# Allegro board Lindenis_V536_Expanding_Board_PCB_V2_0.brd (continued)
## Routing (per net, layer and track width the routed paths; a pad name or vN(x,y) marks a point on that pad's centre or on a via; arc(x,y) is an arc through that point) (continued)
GND_SIGNAL: length 5.5
  TOP w0.406: U8.10 118.62,72.68 CG1.1 v1(119.46,72.43) ; U8.12 v1(117.55,74.88) ; v1(118.31,77.78) FB22.1 v1(118.31,79.45)
  vias: v1(106.05,75.31) v1(106.68,73.66) v1(107.06,70.74) v1(107.19,68.07) v1(108.08,75.06) v1(108.97,67.06) v1(109.35,64.9) v1(109.86,68.07) v1(110.24,69.6) v1(110.24,65.91) v1(110.74,72.26) v1(112.9,64.9) v1(113.41,67.94) v1(113.41,65.91) v1(113.92,72.52) v1(114.3,75.69) v1(114.3,74.8) v1(114.43,66.8) v1(114.68,73.66) v1(114.81,72.52) v1(114.81,70.61) v1(115.19,68.83) v1(115.7,74.68) v1(115.7,72.77) v1(115.82,75.56) v1(116.71,75.82) v1(118.01,82.68) v1(118.11,80.9) v1(118.87,76.07) v1(119.05,80.95) v1(119.13,77.09) v1(119.25,80.14) v1(119.51,74.8) v1(119.59,78.19) v1(120.52,73.28) v1(121.41,80.52) v1(121.41,78.99) v1(121.41,77.22) v1(121.41,74.93) v1(122.05,80.9) v1(122.3,80.14)
VBAT: length 8
  BOTTOM w0.508: 31.58,80.77 J11.7 ; J11.7 33.44,80.77 ; J11.7 32.51,81.7 ; J1.1 7.84,75.18 ; J1.1 7.84,73.53 ; J1.1 7.01,74.35 ; J1.1 8.67,74.35 ; 35.05,81.7 J11.5 34.12,80.77
  vias: v2(56.39,71.12) v2(56.39,70.36) v2(57.4,71.12) v2(57.4,70.36)
VCC33-AUDIO: length 8
  BOTTOM w0.254: R183.1 64.59,14.72 U23.7
  BOTTOM w0.508: C196.1 R183.1
  BOTTOM w0.762: FB12.2 62.16,17.14 C469.1 64.7,16.29 C196.1
VCC-1V8: length 8.9
  TOP w0.305: J7.18 122.92,42.06 122.68,42.29 122.95,42.56 J7.19 125.35,42.56 v1(125.91,42)
  TOP w0.508: U24.5 117.62,48.45 C302.2 118.97,48.21 C304.2
  BOTTOM w0.305: TP63.1 126.33,42.42 v1(125.91,42)
VCC-3V3: length 227.3
  TOP w0.254: v1(39.37,13.84) v1(39.37,14.35) ; v1(39.37,14.35) 39.02,14.7 UM2.21 ; v1(39.37,14.35) 39.32,14.3 UM2.20 ; v1(39.02,56.08) 41.55,58.62 41.55,60.83 40.54,61.85 39.27,61.85 39.09,61.67 v2(36.83,61.67) ; R531.2 v1(121.79,64.9) ; RL57.1 20.62,16.79 DL7.1 v1(21.21,17.02) ; UM2.23 38.98,15.5 v1(39.37,15.11) 39.36,15.1 UM2.22 ; R533.2 v1(121.79,64.01) ; J80.1 11.1,24.77 v1(11.81,24.05) ; R532.2 v1(121.79,65.79) ; RL12.1 15.57,16.23 DL6.1 v1(16.38,17.14) ; R550.1 v1(8.43,11.6) ; v1(77.98,81.03) 77.6,81.41 56.13,81.41 J36.2 ; R420.2 31.52,48.62 U51.1
  TOP w0.406: R192.1 C209.2 103.59,13.97 102.41,13.97 U902.7 ; RM53.2 RM7.2 ; R237.1 39.67,36.87 v1(39.06,36.26) U32.16 ; R420.2 C314.2 C313.2 ; v1(103,69.93) RG1.2 RG2.2 102.11,72.36 101.68,72.79 R13.2 101.68,73.94 Q2.1 ; U32.24 v1(39.05,41.46)
  TOP w0.508: DH12.1 v2(104.77,18.8) ; R238.1 R241.2 25.34,34.8 C328.1 ; v2(104.77,15.24) 104.69,15.32 R192.1 ; J11.8 33.44,78.23 ; J11.8 31.58,78.23 ; J11.8 32.51,79.16 ; RM4.2 v2(21.34,73.03) ; C313.2 v2(31.75,49.78) ; 54.86,81.67 J36.2 ; J36.2 53.86,82.68 ; J36.2 54.86,83.68 ; J11.6 35.05,79.16 ; J11.6 35.98,78.23 ; J11.6 34.12,78.23 ; U11.14 95.5,78.53 ; U11.14 96.43,77.6 ; U11.14 100.33,72.77 v1(100.33,70.23) 100.33,61.85 100.91,61.27 RP84.2 ; U11.14 95.5,76.67 ; RM7.2 36.78,61.72 v2(36.83,61.67)
  L3SIG w0.508: U11.14 95.5,78.53 ; U11.14 94.58,77.6 ; U11.14 95.5,76.67 ; U11.14 96.43,77.6
  BOTTOM w0.254: v1(11.81,24.05) 11.86,24 12.57,24 13.59,22.99 13.59,19.94 v1(16.38,17.14) 14.73,15.49 14.73,12.83 13.08,11.18 11.68,11.18 11.26,11.6 v1(8.43,11.6) ; v1(121.79,65.79) v1(121.79,64.9) v1(121.79,64.01)
  BOTTOM w0.406: v1(16.38,17.14) 16.51,17.02 v1(21.21,17.02) 33.27,17.02 ; v1(100.33,70.23) 102.69,70.23 v1(103,69.93) 108.92,64.01 v1(121.79,64.01) ; v1(39.05,41.46) v1(39.05,37.85) 39.05,36.27 v1(39.06,36.26) 39.06,32.38 U12.14
  BOTTOM w0.508: U12.13 37.64,29.79 ; U12.13 37.64,28.14 ; U12.13 36.81,28.96 ; U12.13 38.47,28.96 ; U11.14 96.43,77.6 ; U11.14 95.5,78.53 ; U11.14 95.5,76.67 ; 54.86,81.67 J36.2 ; J36.2 54.86,83.68 ; J36.2 53.86,82.68 ; J36.2 55.87,82.68 ; U12.14 38.47,30.96 ; U12.14 37.64,30.14 ; U12.14 37.64,31.79 ; RC1.1 v2(90.55,20.08) ; J11.8 30.73,76.45 28.58,76.45 25.15,73.03 v2(21.34,73.03)
  BOTTOM w0.762: R39.1 36.96,76.33 J11.6 J11.8
  vias: v1(46.61,83.19) v1(46.61,82.68) v1(78.49,81.03) v1(81.03,81.03) v1(81.53,81.03) v2(23.88,35.94) v2(23.88,35.18) v2(24.77,35.94) v2(46.48,60.58) v2(47.23,60.62) v2(48.01,60.63) v2(80.64,63.25) v2(81.15,63.75) v2(81.66,64.39) v2(97.16,78.23) v2(97.16,77.47) v2(100.08,60.33) v2(100.33,55.37) v2(100.84,60.33) v2(101.09,55.37)
VCC-5V: length 59.6
  TOP w0.254: v1(105.92,17.65) 107.19,17.65 107.7,17.14 RH18.1 RH17.1
  TOP w0.305: v1(108.58,12.83) 108.66,12.75 109.6,12.75 110.43,11.92 JH1.18
  TOP w0.406: v1(102.87,27.3) 102.87,34.98 CL60.1 ; v1(108.58,12.83) 107.7,13.72 CH2.1
  TOP w0.508: U22.1 53.31,76.13 ; U22.1 52.51,75.33 ; U22.1 54.11,75.33 ; 87.88,76.67 U11.8 ; U11.8 88.81,77.6 ; U11.8 86.96,77.6 ; J11.3 37.59,81.7 ; J11.3 38.52,80.77 ; J11.3 37.59,79.84 ; 39.2,80.77 J11.1 ; J11.1 40.13,81.7 ; J11.1 40.13,79.84 ; J11.1 41.06,80.77
  L3SIG w0.508: 53.31,74.53 U22.1 52.51,75.33 ; 37.59,79.84 J11.3 ; J11.3 38.52,80.77 ; J11.3 36.66,80.77 ; J11.3 37.59,81.7 ; J11.1 40.13,81.7 ; J11.1 41.06,80.77 ; J11.1 39.2,80.77 ; J11.1 40.13,79.84
  BOTTOM w0.406: v1(108.58,12.83) 107.7,12.83 105.92,14.61 v1(105.92,17.65) 105.92,18.92 105.28,19.56 104.67,19.56 104.27,19.96 104.27,24.38 102.87,25.78 v1(102.87,26.54)
  BOTTOM w0.508: U11.8 87.5,77.98 C458.2 88.36,79.84 C457.2 ; U11.8 88.81,77.6 ; U11.8 87.88,78.53
  vias: v1(103.38,27.3) v1(103.38,26.54) v2(9.91,22.61) v2(9.91,21.84) v2(9.91,21.08) v2(9.91,15.37) v2(9.91,14.61) v2(10.67,22.61) v2(10.67,21.84) v2(10.67,21.08) v2(10.67,15.37) v2(10.67,14.61) v2(11.43,15.88) v2(12.19,15.88) v2(37.34,20.95) v2(37.84,21.62) v2(38.1,20.95) v2(38.61,21.59) v2(52.32,71.12) v2(52.32,70.36) v2(52.45,60.48) v2(53.09,71.12) v2(53.09,70.36) v2(53.21,60.48) v2(53.85,71.12) v2(53.85,70.36) v2(53.98,60.48) v2(54.74,60.48) v2(55.5,60.48)
VCC-PE: length 29
  TOP w0.406: RP85.1 41.57,70.91 v1(42.8,72.14) ; v1(41.73,79.76) v1(45.97,79.76)
  BOTTOM w0.406: 54.36,79.5 53.59,78.74 49.28,78.74 48.26,79.76 v1(45.97,79.76) ; 54.36,79.5 54.36,76.93 55.31,75.98 U22.3 ; 54.36,79.5 54.36,79.71 RP82.1 ; v1(41.73,79.76) 41.91,79.58 41.91,78.11 43.31,76.71 43.31,72.54 42.9,72.14 v1(42.8,72.14)
VCC-RTC: length 45.3
  TOP w0.508: 54.99,68.91 v2(54.99,70.23) ; J11.20 17.93,78.23 22.17,73.99 v1(33.17,73.99) ; v2(39.67,73.87) 42.46,73.87 v2(44.2,72.14)
  BOTTOM w0.508: v2(54.99,70.23) 54.99,71.5 54.36,72.14 50.42,72.14 48.77,73.79 44.7,73.79 44.2,73.28 v2(44.2,72.14) ; v2(39.67,73.87) C84.2 36.16,73.87 C385.2 34.19,74.22 D608.2 33.43,74.24 v1(33.17,73.99)
VCC-WIFI-IO: length 25.4
  TOP w0.508: v2(39.13,55.37) 42.04,58.27 42.04,61.21 40,63.25 40,68.58 38.82,69.77 RP81.1
  BOTTOM w0.508: U13.14 35.63,55.54 36.73,56.64 C467.1 40.22,55.66 C170.1 v2(39.13,55.37)
4G-STATUS: length 82.6
  TOP w0.102: v1(89.28,34.8) 89.28,23.72 86.64,21.08 80.52,21.08 79.12,19.68 U901.105 ; v1(119.13,49.15) 118.75,49.53 111.51,49.53 110.11,50.93 108.33,50.93 103.12,56.13 97.92,56.13 v1(97.03,55.24)
  BOTTOM w0.102: U27.49 123.67,48.24 123.19,47.75 123.19,47.37 122.81,46.99 122.43,46.99 120.27,49.15 v1(119.13,49.15) ; v1(97.03,55.24) 95.45,53.67 95.45,36.14 94.11,34.8 v1(89.28,34.8)
ALDO1: length 152.9
  TOP w0.254: v1(78.61,79.12) v1(81.66,79.12) ; v1(92.81,22.33) 92.81,22.37 92.76,22.42 92.76,40.7 93.52,41.46 93.52,50.11 91.43,52.21 v2(90.42,52.21) ; v1(96.75,18.39) 96.75,14.63 99.1,12.28 RK1.2
  TOP w0.508: v2(83.06,54.99) 83.06,65.15 v1(82.33,65.88) 81.91,66.29 72.26,66.29 71.73,66.83 48.59,66.83 47.37,68.05 U901.38 ; v2(88.39,54.74) 88.39,54.24 v2(90.42,52.21)
  TOP w0.762: J11.16 22.35,77.32 23.49,76.17 35.64,76.17 36.09,75.72 42.77,75.72 47.37,71.12 U901.38
  BOTTOM w0.254: v1(82.33,65.88) 82.33,66.35 84.71,68.73 84.71,70.43 84,71.15 84,72.34 81.56,74.78 81.56,79.02 v1(81.66,79.12) ; v1(78.61,79.12) 78.61,79.02 78.16,78.56 77.64,78.56 77.39,78.82 RK8.2 ; v1(92.81,22.33) v1(96.75,18.39)
  BOTTOM w0.508: v2(83.06,54.99) 88.14,54.99 v2(88.39,54.74)
ALDO3: length 256.8
  TOP w0.254: JL6.4 v1(124.72,64.64) ; CL13.1 v1(123.83,61.34)
  TOP w0.406: 46.32,67.98 48.16,66.14 56.97,66.14 57.38,65.74 81.58,65.74 82.4,64.92 v1(82.4,54.99) ; v1(43,69.85) 42.67,69.51 42.67,60.66 v1(42.6,60.58) ; v1(93.55,65.68) 91.68,65.68 90.65,64.66 90.65,58.78 v1(90.75,58.67) 93.95,55.47 93.95,41.28 93.19,40.52 93.19,22.89 93.47,22.61 v1(93.47,22.32) ; v2(44.73,69.98) 45.54,69.16 U901.39 ; CL13.1 v1(123.23,60.75) ; U902.3 99.17,14.8 C210.2 99.1,15.07 97.36,16.82 v1(97.36,18.44)
  TOP w0.508: 46.32,67.98 46.1,68.2 U901.39 46.1,71.25 42.67,74.68 39.17,74.68 38.76,74.27 35.51,74.27 34.52,75.26 23.06,75.26 21.08,77.24 21.08,79.5 J11.17
  BOTTOM w0.254: v1(42.6,60.58) 42.6,60.46 40.66,58.52 35.89,58.52 34.42,57.05 27.74,57.05 26.85,56.16 23.32,56.16 21.32,54.16 Q23.1 ; R78.2 R77.2 86.01,80.32 86.01,83.09 86.74,83.82 88.01,83.82 89.15,82.68 J35.2 ; v1(93.47,22.32) 93.47,22.25 96.9,18.82 96.98,18.82 v1(97.36,18.44) ; v1(124.72,64.64) 124.72,62.23 v1(123.83,61.34)
  BOTTOM w0.406: J35.2 90.12,82.68 94.23,78.56 94.23,76.15 94.36,76.02 94.36,73.28 93.55,72.47 v1(93.55,65.68) 95.76,63.47 95.76,62.61 98.81,59.56 122.05,59.56 v1(123.23,60.75) ; v1(82.4,54.99) 82.4,55.22 85.85,58.67 v1(90.75,58.67) ; v1(43,69.85) 43,69.87 43.11,69.98 v2(44.73,69.98)
ANT-BIAS: length 2.2
  TOP w0.102: U8.9 118.87,71.58 CG1.2
AP-WAKE-4G: length 39.2
  TOP w0.102: U901.108 82.93,19.81 83.31,20.19 86.61,20.19 90.3,23.88 v1(90.3,33.78)
  BOTTOM w0.102: U27.72 107.97,32.87 107.06,33.78 v1(90.3,33.78)
AP-WAKE-BT: length 73.7
  TOP w0.102: v1(87.12,66.55) 87.38,66.8 U901.155
  BOTTOM w0.102: 87,66.67 87,66.67 87,71.71 R528.2 ; 87,66.67 86.62,66.67 81.08,61.14 45.11,61.14 41.17,57.2 36.41,57.2 34.67,55.47 34.67,53.88 U13.13 ; 87,66.67 v1(87.12,66.55)
AUDIO-L: length 6.4
  TOP w0.254: v1(54.61,13.21) 54.53,13.29 D609.2 53.56,12.87 53.56,10.75 J79.4
  BOTTOM w0.254: R180.2 54.86,13.46 v1(54.61,13.21)
AUDIO-R: length 25.8
  TOP w0.254: v1(58.17,10.41) 56.9,11.68 56.9,12.57 55.71,13.76 ; 55.71,13.76 D610.2 ; 55.71,13.76 55.71,13.16 54.36,11.81 54.36,7.25 J79.2
  BOTTOM w0.254: R181.1 66.04,13.34 66.67,12.7 66.67,11.18 65.91,10.41 v1(58.17,10.41)
AVDUSB: length 21.3
  TOP w0.508: U8.7 116.08,67.48 115.57,66.97 115.57,61.98 114.3,60.71 111.25,60.71 109.86,59.31 104.14,59.31 102.87,60.58 RP75.2
BATT-VCC-3V3: length 8.4
  BOTTOM w0.406: R43.2 41.77,71.82 U2.1 41.07,71.82 C85.2 41.07,74.8 D7.2
  BOTTOM w0.508: U3.1 45.17,70.99 42.59,70.99 R43.2
BATT-VCC-RTC: length 7.5
  BOTTOM w0.254: R45.2 37.64,70.27 38.63,71.26 38.63,71.82
  BOTTOM w0.508: D608.1 34.19,72.85 C81.2 36.48,72.18 C82.2 38.26,72.18 38.63,71.82 U2.5
BB-PWREN: length 31.8
  TOP w0.102: v1(89.92,43.18) 89.92,23.78 86.58,20.45 82.42,20.45 81.66,19.68 U901.107
  BOTTOM w0.102: v1(89.92,43.18) 89.66,42.93 88.9,42.93 88.6,42.63 RL70.2
BB_PW: length 26.6
  TOP w0.102: RL38.2 99.87,38.31 97.49,40.68 94.15,40.68 93.6,40.13 93.6,23.93 93.9,23.62 U901.121
BLDO1: length 32.3
  TOP w0.508: U901.40 43.94,69.14 43.94,69.89 43.43,70.4 43.19,70.4 43.18,70.4 42.72,70.4 42.72,70.4 41.91,69.6 41.28,69.6 40.72,70.15 RP85.2 RP81.2 39.67,72.39 38.55,73.51 35.33,73.51 34.24,74.6 22.63,74.6 19.81,77.42 J11.18
BT-RST-N: length 72.8
  TOP w0.102: U901.156 94.49,68.07 93.47,67.06 86.55,67.06 v1(86.52,67.02)
  BOTTOM w0.102: R526.2 86.74,71.08 86.74,67.25 v1(86.52,67.02) 86.52,66.86 81,61.34 45.03,61.34 41.09,57.4 36.32,57.4 33.84,54.93 U13.12
BT-UART-CTS: length 73.8
  TOP w0.102: v1(85.91,67.5) 85.95,67.46 93.25,67.46 94.36,68.58 U901.1
  BOTTOM w0.102: v1(85.91,67.5) 85.95,67.46 85.95,66.89 80.81,61.75 44.86,61.75 40.92,57.81 36.15,57.81 34.6,56.26 28.32,56.26 27.63,55.57 U13.6
BT-UART-RTS: length 75.1
  TOP w0.102: v1(86.36,67.82) 86.36,67.82 92.58,67.82 93.09,68.33 U901.2
  BOTTOM w0.102: U13.8 29.63,55.41 30.1,55.88 34.51,55.88 36.24,57.61 41,57.61 44.94,61.54 80.89,61.54 86.16,66.82 86.16,67.17 86.36,67.37 v1(86.36,67.82) 86.36,70.57 R525.2
BT-UART-RX: length 68.5
  TOP w0.102: U901.9 84.58,68.53 84.58,67.16 84.61,67.13 v1(84.61,67.11)
  BOTTOM w0.102: U13.2 24.58,55.88 27.08,55.88 27.91,56.72 34.49,56.72 35.98,58.22 40.75,58.22 44.69,62.15 80.59,62.15 84.61,66.17 v1(84.61,67.11)
BT-UART-TX: length 66.9
  TOP w0.102: 85.47,68.91 85.47,68.07 v1(84.96,67.56)
  BOTTOM w0.102: U13.4 26.45,54.93 28.04,56.52 34.57,56.52 36.07,58.01 40.84,58.01 44.77,61.95 80.72,61.95 84.96,66.19 v1(84.96,67.56)
BT-WAKE-AP: length 112.3
  TOP w0.102: v1(87.25,23.24) 68.43,23.24 65.25,20.07 52.2,20.07 46.61,25.65 46.61,35.53 47.45,36.36 47.45,52.27 48.06,52.88 49.66,52.88 50.88,54.1 50.88,59.9 51.03,60.05 51.03,60.47 50.82,60.68 50.02,60.68 49.66,60.33 v1(49.66,60.33) ; U901.120 v1(93.98,22.35)
  BOTTOM w0.102: v1(87.25,23.24) 93.09,23.24 v1(93.98,22.35) ; v1(49.66,60.33) 49.5,60.17 47.35,60.17 38.74,51.56 34.42,51.56 33.63,52.35 U13.11
CLKOUT-125M: length 1.8
  TOP w0.102: UM1.35 25.2,67.42 RM14.1
CSI0-D0: length 22.7
  BOTTOM w0.102: U22.11 62.48,76.15 62.48,78.11 63.5,79.12 71.32,79.12 73.22,77.23 73.22,76.18 R434.2
CSI0-D1: length 18.7
  BOTTOM w0.102: U22.12 63.31,78.35 63.83,78.87 71.2,78.87 72.82,77.24 72.82,76.12 76.58,72.36 R435.2
CSI0-D2: length 18.2
  BOTTOM w0.102: U22.13 64.14,76.5 64.14,77.98 64.77,78.61 69.32,78.61 70.31,77.62 70.31,76.94 70.93,76.32 71.79,76.32 74.17,73.94 R436.2
CSI0-D3: length 11.5
  BOTTOM w0.102: R437.2 71.04,72.26 70.13,72.26 68.2,74.19 68.2,77.57 67.64,78.13 66.11,78.13 U22.14
CSI0-D4: length 4.9
  BOTTOM w0.102: R438.2 69.98,71.98 67.31,74.65 U22.15
CSI0-D5: length 6.9
  BOTTOM w0.102: U22.16 66.42,76.44 66.42,75.03 68,73.46 68,71.75 R439.2
CSI0-D6: length 15.5
  BOTTOM w0.102: R440.2 67.54,71.77 67.54,73.28 66.17,74.65 66.17,75.82 65.66,76.33 64.9,76.33 64.39,76.83 64.39,77.72 65.02,78.36 68.1,78.36 68.45,78 68.45,76.18 U22.17
CSI0-D7: length 7.3
  BOTTOM w0.102: U22.18 70.36,76.28 70.36,74.68 72.9,72.14 R441.2
CSI0-HSYNC: length 33
  BOTTOM w0.102: U22.9 60.31,76.33 58.8,76.33 58.29,76.83 58.29,78.87 60.2,80.77 72.19,80.77 77.39,75.56 77.39,74.54 R432.2
CSI0-MCLK: length 26.5
  TOP w0.102: v1(81.03,71.5) v1(78.49,71.5)
  BOTTOM w0.102: R431.2 81.07,71.54 v1(81.03,71.5) ; v1(78.49,71.5) 78.49,71.73 78.19,72.02 78.19,72.53 77.86,72.86 77.36,72.86 73.85,76.37 73.85,77.33 71.5,79.68 62.32,79.68 C456.1 61.31,78.66 U22.10
CSI0-PCLK: length 36.4
  BOTTOM w0.102: U22.5 57.31,75.91 56.26,76.96 56.26,78.49 59.08,81.31 72.44,81.31 78.23,75.51 78.23,74.22 79.81,72.64 82.04,72.64 83.06,71.63 R430.2
CSI0-PWR: length 14.3
  TOP w0.102: v1(63.25,71.73) 63.14,71.63 59.31,71.63 v1(59.05,71.37)
  BOTTOM w0.102: v1(59.05,71.37) 59.05,71.75 56.39,74.42 54.74,74.42 54.36,74.8 54.36,76.28 U22.2 ; R522.2 63.3,71.67 v1(63.25,71.73)
CSI0-RSET: length 16.1
  TOP w0.102: v1(59.05,70.87) 59.56,71.37 v1(65.79,71.37)
  BOTTOM w0.102: R442.2 65.96,71.54 v1(65.79,71.37) ; U22.4 56.26,76.38 56.26,74.93 59.56,71.63 59.56,71.37 v1(59.05,70.87)
CSI0-SCK: length 9.6
  TOP w0.102: v1(59.87,70.36) 60.07,70.15 U901.28
  BOTTOM w0.102: v1(59.87,70.36) 59.87,71.83 58.29,73.41 58.29,75.95 57.31,76.93 U22.6
CSI0-SDA: length 7.8
  TOP w0.102: U901.27 61.34,69.39 v1(60.38,70.36)
  BOTTOM w0.102: U22.7 58.7,74.72 58.7,73.51 60.38,71.83 v1(60.38,70.36)
CSI0-VSYNC: length 26.2
  BOTTOM w0.102: R433.2 79.12,72.44 74.43,77.14 74.43,77.52 71.7,80.24 60.81,80.24 59.31,78.74 U22.8
CTP-INT: length 86.3
  TOP w0.102: JL6.2 125.11,63.64 123.7,62.23 C464.2 122.83,61.83 121.72,61.83 121.36,61.47 121.36,60.27 120.14,59.05 112.39,59.05 110.46,57.12 105.51,57.12 105.43,57.05 104.8,57.05 v1(104.77,57.02) ; v1(88.14,57.53) 85.34,54.74 85.34,53.21 91.31,47.24 91.31,22.13 93.38,20.07 93.98,20.07 94.36,19.68 U901.117
  BOTTOM w0.102: v1(88.14,57.53) 88.39,57.78 91.11,57.78 92.05,58.72 95.58,58.72 97.21,57.1 104.7,57.1 v1(104.77,57.02)
CTP-RST: length 87.4
  TOP w0.102: JL6.3 123.96,64.14 v1(123.83,64.01) R533.1 C465.2 123.1,63.12 122.7,63.52 121.81,63.52 121.16,62.87 121.16,60.36 120.06,59.26 112.31,59.26 110.46,57.4 v1(105.28,57.4) ; v1(87.63,57.53) 85.14,55.04 85.14,53.13 91.11,47.16 91.11,22.05 93.09,20.07 U901.116
  BOTTOM w0.102: v1(87.63,57.53) 87.64,57.53 88.27,58.17 91.19,58.17 91.95,58.93 95.66,58.93 97.29,57.3 104.41,57.3 104.49,57.38 105.26,57.38 v1(105.28,57.4)
DC1SW: length 275.7
  TOP w0.254: v1(121.54,48.51) 121.79,48.77 121.79,52.32 ; v2(33.78,9.4) 33.78,10.08 RL47.2 ; R269.2 114.98,48.68 115.44,49.15 v1(118.62,49.15)
  TOP w0.305: J7.38 122.95,52.06 122.68,52.32 122.91,52.56 J7.39 125.56,52.56 v1(125.95,52.17) ; C463.2 v2(121.23,56.01) 121.23,56.44 120.1,57.57 R320.2
  TOP w0.508: J11.15 23.62,79.5 23.62,77.65 24.26,77.01 36.02,77.01 36.58,76.45 43.18,76.45 48.64,70.99 U901.37 48.64,68.07 49.15,67.56 71.88,67.56 72.39,67.06 82.04,67.06 83.82,65.28 v2(83.82,55.75) 83.82,54.36 83.31,53.85 53.85,53.85 51.94,51.94 v2(51.94,51.69) ; v2(48.13,9.4) v2(33.78,9.4) ; v2(47.37,34.04) 47.55,33.86 47.55,25.91 v2(52.68,20.78)
  BOTTOM w0.254: v1(121.54,48.51) 120.4,49.66 119,49.66 118.62,49.28 v1(118.62,49.15)
  BOTTOM w0.305: TP66.1 v1(125.95,52.17)
  BOTTOM w0.508: v2(33.78,9.4) 33.15,8.76 30.35,8.76 28.52,10.59 17.75,10.59 C111.1 17.37,10.21 C112.1 16.51,7.37 15.37,6.22 15.37,4.45 J82.20 J82.18 ; v2(52.68,20.78) 52.6,20.78 48.13,16.31 v2(48.13,9.4) ; v2(51.94,51.69) 51.89,51.74 48.31,51.74 47.37,50.8 v2(47.37,34.04) ; v2(121.23,56.01) 120.6,55.37 119,55.37 117,57.37 110.45,57.37 109.27,56.18 97.36,56.18 95.38,58.17 92.2,58.17 91.31,57.28 88.9,57.28 87.38,55.75 v2(83.82,55.75)
DM1_USB: length 64.2
  TOP w0.114: U32.27 37.62,43.41 37.77,43.56 v1(39.24,43.56) ; v1(86.74,53.72) 86.76,53.74 87.05,53.74 92.09,48.71 92.39,48.71 v1(92.71,48.39)
  BOTTOM w0.114: v1(86.74,53.72) 86.48,53.72 85.97,53.21 48.44,53.21 40.82,45.59 40.82,44.93 39.44,43.56 v1(39.24,43.56) ; U27.12 92.86,48.24 v1(92.71,48.39)
DM2_USB: length 29.3
  TOP w0.114: J9.3 13.15,37.48 13.26,37.36 14.25,37.36 15.62,38.73 16.68,38.73 D28.1 17.39,38.7 18.76,38.7 21.21,41.15 21.21,45.09 24.38,48.26 27.69,48.26 28.96,46.99 28.96,43.58 29.36,43.18 29.46,43.18 29.7,43.41 U32.2
DM3_USB: length 25.7
  TOP w0.114: J9.7 10.44,37.48 10.55,37.36 11.53,37.36 11.94,36.96 11.94,35.43 12.32,35.05 14.78,35.05 14.95,34.89 16.64,34.89 D29.1 17.39,34.89 18.38,34.89 23.88,40.39 28.32,40.39 29.33,39.38 29.64,39.38 29.77,39.51 U32.8
DM4_USB: length 2.4
  TOP w0.114: U32.11 31.27,37.56 v1(31.5,37.34)
  BOTTOM w0.114: v1(31.5,37.34) 31.62,37.34 TP87.1
DP1_USB: length 64.2
  TOP w0.114: v1(87.12,54.1) 92.21,49.01 92.7,49.01 v1(92.71,49.02) ; U32.28 37.62,44.06 37.82,43.87 38.99,43.87 v1(39.24,44.12)
  BOTTOM w0.114: v1(92.71,49.02) 92.92,49.24 U27.13 ; v1(39.24,44.12) 39.27,44.09 39.55,44.09 40.51,45.06 40.51,45.72 48.31,53.52 85.85,53.52 86.43,54.1 v1(87.12,54.1)
DP2_USB: length 29.3
  TOP w0.114: J9.2 13.15,36.94 13.26,37.06 14.38,37.06 15.75,38.43 16.6,38.43 D27.1 17.39,38.39 18.88,38.39 21.51,41.02 21.51,44.96 24.51,47.96 27.56,47.96 28.65,46.86 28.65,43.46 29.23,42.88 29.61,42.88 29.72,42.76 U32.3
DP3_USB: length 25.7
  TOP w0.114: U32.9 29.77,38.86 29.56,39.07 29.2,39.07 28.19,40.08 24,40.08 18.5,34.58 17.39,34.58 D30.1 16.64,34.58 14.82,34.58 14.66,34.75 12.19,34.75 11.63,35.31 11.63,36.83 11.41,37.06 10.55,37.06 10.44,36.94 J9.6
DP4_USB: length 2.3
  TOP w0.114: U32.12 31.41,36.91 v1(31.5,36.83)
  BOTTOM w0.114: TP88.1 31.75,36.83 v1(31.5,36.83)
EPHY-CLK-25M: length 1.9
  TOP w0.102: U901.24 v1(65.15,70.1)
  BOTTOM w0.102: RM56.2 v1(65.15,70.1)
FEL: length 60.3
  TOP w0.102: v1(118.11,17.4) 118.28,17.23 RK7.2 ; U901.95 66.42,18.29 66.83,17.88 69.46,17.88 72.01,15.33 72.01,13.84 73.91,11.94 v1(96.9,11.94)
  BOTTOM w0.102: v1(96.9,11.94) 109.6,11.94 111.51,13.84 117.12,13.84 117.6,14.32 117.6,16.89 v1(118.11,17.4)
GPADC0: length 134.3
  TOP w0.102: v1(89.26,65.33) 89.26,65.28 89.18,65.2 89.18,62.38 88.77,61.98 88.77,60.17 84.73,56.13 84.73,52.96 88.9,48.79 88.9,23.88 86.31,21.29 69.93,21.29 68.96,20.32 U901.97 68.96,18.19 69.06,18.08 69.67,18.08 72.26,15.49 72.26,13.88 74,12.14 96.34,12.14 96.49,12.29 98.03,12.29 RK1.1 DK1.2 CK1.2 RK2.2 ; v1(91.57,79.12) 90.8,79.88 81.57,79.88 78.99,82.46 J33.1
  BOTTOM w0.102: v1(91.57,79.12) 91.82,78.87 91.82,74.3 90.75,73.23 90.75,65.7 90.53,65.48 89.41,65.48 v1(89.26,65.33)
GPADC1: length 105.7
  TOP w0.102: v1(90.93,79.12) 90.42,79.63 81.53,79.63 80.9,80.26 78.74,80.26 78.49,80.01 75.79,80.01 v1(75.69,80.11) ; v1(88.85,65.68) 88.85,62.43 88.53,62.12 88.53,61.07 88.52,61.06 88.52,60.21 84.53,56.22 84.53,52.88 88.6,48.81 88.6,24 86.18,21.59 68.96,21.59 67.69,20.32 U901.96
  BOTTOM w0.102: v1(88.85,65.68) 90.45,65.68 90.55,65.79 90.55,73.31 91.62,74.38 91.62,78.44 v1(90.93,79.12) ; v1(75.69,80.11) 75.69,79.89 RK8.1 CK16.2 DK2.2 76.54,82.59 J33.2
GPS-RESETN: length 108.7
  TOP w0.102: v1(97.79,59.82) 99.16,58.45 110.32,58.45 111.74,59.87 117.93,59.87 118.24,60.17 118.24,70.18 117.93,70.48 U8.8 ; U901.57 46.1,46.48 46.53,46.91 46.53,52.5 48.13,54.1 48.72,54.1 v1(48.84,54.23)
  BOTTOM w0.102: R529.2 92.96,65.66 95.38,63.25 95.38,62.23 v1(97.79,59.82) 85.5,59.82 82.43,56.74 80.18,56.74 78.81,55.37 49.99,55.37 v1(48.84,54.23)
HCEC: length 31.4
  TOP w0.102: U901.133 96.01,38.86 100.61,34.26 100.61,26.77 v1(101.98,25.4) ; RH21.1 108.93,18.24 104.44,18.24 103.25,19.43 v1(103.25,19.81)
  BOTTOM w0.102: v1(101.98,25.4) 101.98,25.27 103.25,24 v1(103.25,19.81)
HDMI-CEC: length 8.1
  TOP w0.102: RH16.2 RH21.2 110.77,15.56 110.77,14.12 110.45,13.8 DH5.1 111.13,13.03 111.56,13.03 112.93,11.66 JH1.13
HDMI-SCL: length 8.2
  TOP w0.102: JH1.15 111.93,12.03 111.12,12.83 110.45,12.83 DH4.1 109.56,13.8 109.88,14.12 109.88,15.56 RH19.2 RH17.2
HDMI-SDA: length 8.7
  TOP w0.102: JH1.16 111.43,12.14 111,12.57 110.21,12.57 109.73,13.06 109.33,13.06 DH3.1 108.1,14.29 108.1,15.56 RH18.2 RH20.2
HHPD: length 32
  TOP w0.102: RH5.1 CH1.1 105.33,15.96 v1(102.49,18.8) ; v1(102.49,25.4) 100.81,27.08 100.81,34.35 96.39,38.77 96.39,39.83 96.09,40.13 U901.134
  BOTTOM w0.102: v1(102.49,18.8) 102.87,18.8 103.63,19.56 103.63,24.13 102.49,25.27 v1(102.49,25.4)
HSCL: length 29
  TOP w0.102: v1(102.49,19.81) 104.27,18.03 108.85,18.03 109.47,17.41 RH19.1 ; v1(100.95,25.39) 100.2,26.14 100.2,32.89 96.77,36.32 U901.131
  BOTTOM w0.102: v1(102.49,19.81) 102.49,23.85 v1(100.95,25.39)
HSDA: length 27.4
  TOP w0.102: U901.132 95.89,37.59 100.41,33.07 100.41,26.47 v1(101.47,25.4) ; v1(102.49,19.3) 104.52,17.27 106.3,17.27 106.76,16.81 RH20.1
  BOTTOM w0.102: v1(101.47,25.4) 102.84,24.03 102.84,19.66 v1(102.49,19.3)
HTX0N: length 34.5
  TOP w0.097: JH1.9 114.93,11.93 115.04,12.04 115.28,12.04 115.38,12.14 115.38,13.17 115.2,13.35 UH2.9 UH2.2 115.2,14.95 115.29,15.05 115.29,15.62 112.65,18.26 112.65,19.35 110.03,21.97 99.69,21.97 97.41,24.26 97.41,27.98 96.21,29.18 96.11,29.18 96.02,29.08 96.02,28.8 95.92,28.7 U901.125
HTX0P: length 34.7
  TOP w0.097: U901.126 95.92,29.97 96.02,29.88 96.02,29.59 96.11,29.5 96.34,29.5 97.73,28.11 97.73,24.39 99.83,22.29 110.16,22.29 112.97,19.49 112.97,18.39 115.61,15.75 115.61,15.05 115.7,14.95 UH2.1 UH2.10 115.7,12.13 115.93,11.9 JH1.7
HTX1N: length 38.2
  TOP w0.097: JH1.6 116.43,11.78 116.71,12.06 116.89,12.06 117.11,12.29 117.11,12.85 117.22,12.95 117.22,13.26 117.13,13.35 UH1.6 UH1.5 117.13,14.95 117.22,15.05 117.22,15.37 116.84,15.75 116.33,15.75 113.47,18.61 113.47,20 110.55,22.92 100.27,22.92 98.3,24.89 98.3,29.63 96.21,31.72 96.11,31.72 96.02,31.62 96.02,31.34 95.92,31.24 U901.127
HTX1P: length 38.3
  TOP w0.097: U901.128 95.92,32.51 96.02,32.42 96.02,32.13 96.11,32.04 96.34,32.04 98.62,29.76 98.62,25.02 100.4,23.24 110.69,23.24 113.79,20.13 113.79,18.74 116.46,16.07 116.97,16.07 117.53,15.5 117.53,15.05 117.63,14.95 UH1.4 UH1.7 117.63,13.35 117.53,13.26 117.53,12.82 117.43,12.72 JH1.4
HTX2N: length 41.7
  TOP w0.097: JH1.3 117.93,11.88 118.24,12.19 118.41,12.19 118.5,12.29 118.5,12.71 118.79,13 118.79,13.14 118.63,13.3 UH1.9 UH1.2 118.63,14.95 118.72,15.05 118.72,15.32 117.37,16.66 116.69,16.66 114.3,19.05 114.3,20.7 111,24 100.84,24 99.31,25.53 99.31,31.62 96.68,34.26 96.11,34.26 96.02,34.16 96.02,33.88 95.92,33.78 U901.129
HTX2P: length 41.9
  TOP w0.097: JH1.1 118.93,11.82 118.82,11.93 118.82,12.58 119.13,12.89 UH1.10 UH1.1 119.13,14.95 119.03,15.05 119.03,15.45 117.51,16.98 116.82,16.98 114.62,19.18 114.62,20.83 111.13,24.32 100.97,24.32 99.63,25.66 99.63,31.75 96.81,34.58 96.11,34.58 96.02,34.67 96.02,34.96 95.92,35.05 U901.130
HTXCN: length 31.5
  TOP w0.097: JH1.12 113.43,11.94 113.52,12.04 113.78,12.04 113.88,12.14 113.88,13.17 113.7,13.35 UH2.6 UH2.5 113.7,14.95 113.88,15.14 113.88,15.66 111.69,17.85 111.69,18.87 109.47,21.08 99.06,21.08 96.59,23.55 96.59,26.35 96.3,26.64 96.11,26.64 96.02,26.54 96.02,26.26 95.92,26.16 U901.123
HTXCP: length 31.7
  TOP w0.097: U901.124 95.92,27.43 96.02,27.34 96.02,27.05 96.11,26.96 96.43,26.96 96.9,26.48 96.9,23.69 99.19,21.4 109.61,21.4 112,19 112,17.99 114.2,15.79 UH2.4 UH2.7 114.2,12.04 114.43,11.81 JH1.10
I2S2-BCLK: length 7.8
  BOTTOM w0.102: R527.1 87.63,73.41 88.9,74.68 88.9,75.77 88.6,76.07 86.87,76.07 U11.6
I2S2-DIN: length 2.7
  BOTTOM w0.102: U11.7 86.74,73.91 R528.1
I2S2-DOUT: length 5.9
  BOTTOM w0.102: R529.1 93.98,73.58 93.98,75.69 92.96,76.71 U11.12
I2S2-LRCK: length 2.5
  BOTTOM w0.102: U11.5 85.34,73.32 R526.1
I2S2-MCLK: length 5.7
  BOTTOM w0.102: U11.4 84.12,76.28 84.12,73.65 R525.1
INTB: length 6.6
  TOP w0.102: UM1.31 26.8,66.05 26.97,66.05 29.38,68.45 30.93,68.45 RM20.1
LCD-CLK: length 36.3
  TOP w0.102: U901.70 43.86,29.97 42.65,28.76 42.65,26.9 39.9,24.16 32.59,24.16 30.63,22.2 30.63,7.52 32.13,6.02 J82.7
LCD-D3: length 57.3
  TOP w0.102: U901.58 42.16,45.21 41.66,44.7 41.66,32.6 39.8,30.74 39.8,28.37 38.89,27.46 31.42,27.46 26.03,22.07 v1(26.03,10.03)
  BOTTOM w0.102: v1(26.03,10.03) 26.42,9.65 28.32,9.65 30.61,7.37 30.61,6.48 J82.9
LCD-D4: length 41.4
  TOP w0.102: J82.10 30.73,4.06 30.73,5.79 29.59,6.93 29.59,8 29.86,8.27 29.86,22.57 32.23,24.94 38.96,24.94 41.86,27.84 41.86,29.27 44.27,31.68 44.27,32.21 44.58,32.51 U901.68
LCD-D5: length 46.3
  TOP w0.102: U901.63 43.23,38.86 42.93,38.56 42.93,32.25 40.94,30.27 40.94,28.07 39.18,26.31 32.18,26.31 28.88,23.01 28.88,20.23 28.9,20.21 28.9,17.63 28.88,17.61 28.88,9.19 v1(27.18,7.49)
  BOTTOM w0.102: v1(27.18,7.49) 27.05,7.37 J82.11
LCD-D6: length 42.9
  TOP w0.102: J82.12 27.05,3.05 28.19,4.19 28.19,6.99 29.62,8.41 29.62,22.68 32.08,25.15 38.88,25.15 41.66,27.92 41.66,29.36 44.07,31.77 44.07,33.48 44.37,33.78 U901.67
LCD-D7: length 44
  TOP w0.102: J82.13 25.78,6.73 27.56,6.73 29.39,8.56 29.39,22.78 31.95,25.35 38.79,25.35 41.4,27.96 41.4,29.72 43.64,31.95 43.64,34.75 43.94,35.05 U901.66
LCD-D10: length 50.9
  TOP w0.102: U901.64 43.48,37.59 43.18,37.29 43.18,32.14 41.2,30.16 41.2,28.04 39.22,26.06 32.31,26.06 29.15,22.9 29.15,8.83 27.43,7.11 24.51,7.11 23.49,6.1 23.49,3.94 J82.14
LCD-D11: length 44.6
  TOP w0.102: U901.69 44.12,31.24 42.06,29.19 42.06,27.75 39.05,24.74 32.41,24.74 30.1,22.43 30.1,7.37 29.95,7.21 v1(29.95,7.15)
  BOTTOM w0.102: v1(29.95,7.15) 28.76,8.33 24.84,8.33 J82.15
LCD-D12: length 58.4
  TOP w0.102: v1(24,8.89) 26.54,8.89 27.43,9.78 27.43,22.71 31.78,27.05 39.06,27.05 40.21,28.2 40.21,30.57 42.06,32.43 42.06,42.37 42.37,42.67 U901.60
  BOTTOM w0.102: J82.16 21.72,2.92 20.7,3.94 20.7,6.2 23.39,8.89 v1(24,8.89)
LCD-D13: length 151.1
  TOP w0.102: v1(27.05,10.03) 27.05,22.71 31.6,27.25 38.97,27.25 40,28.29 40,30.66 41.86,32.51 41.86,43.64 42.16,43.94 U901.59 46.1,43.94 46.74,44.58 46.74,52.42 47.81,53.49 49.05,53.49 49.35,53.8 v1(49.35,54.23) ; v1(104.27,57.66) 104.14,57.53 104.14,55.75 v1(104.27,55.63) ; R342.1 119.51,52.2 v1(118.73,51.42)
  BOTTOM w0.102: v1(104.27,55.63) 111.51,55.63 112.06,56.18 114.11,56.18 118.73,51.56 v1(118.73,51.42) ; v1(49.35,54.23) 49.48,54.1 50.55,54.1 51.21,54.76 79.06,54.76 80.43,56.13 82.68,56.13 85.76,59.21 96.55,59.21 97.7,58.06 103.86,58.06 v1(104.27,57.66) ; 37.21,5.46 36.58,5.46 34.42,7.62 30.86,7.62 28.45,10.03 v1(27.05,10.03)
LCD-D14: length 52.4
  TOP w0.102: RL47.1 v1(32.89,9.53) 32.89,9.4 34.42,7.87 34.42,5.71 J82.5 ; v1(28.19,11.18) 28.19,22.7 32.05,26.57 39.15,26.57 40.69,28.11 40.69,30.37 42.55,32.23 42.55,39.83 42.85,40.13 U901.62
  BOTTOM w0.102: v1(28.19,11.18) 28.7,11.18 30.35,9.53 v1(32.89,9.53)
LCD-D18: length 89
  TOP w0.102: U901.65 46.35,36.32 46.99,36.96 46.99,52.38 47.9,53.29 49.16,53.29 49.86,53.99 v1(49.86,54.48) ; R286.2 113.84,58.25 113.79,58.29 v1(113.79,58.39)
  BOTTOM w0.102: v1(49.86,54.48) 49.87,54.48 50.55,55.17 78.89,55.17 80.26,56.54 82.52,56.54 85.59,59.61 96.72,59.61 97.87,58.47 113.72,58.47 v1(113.79,58.39)
LCD-D19: length 54.9
  TOP w0.102: J82.17 22.48,8.51 26.92,8.51 27.83,9.42 27.83,22.73 31.93,26.82 39.12,26.82 40.44,28.14 40.44,30.48 42.29,32.33 42.29,40.89 42.8,41.4 U901.61
LCD-DC-EN-1: length 2.4
  TOP w0.305: R286.1 R285.1 113.2,56.3 U39.4
LCD-DE: length 34.1
  TOP w0.102: U901.73 44.65,26.16 41.04,22.56 33.82,22.56 32.38,21.12 32.38,9.4 33.66,8.13 33.66,3.94 34.67,2.92
LCD-HSYNC: length 36.1
  TOP w0.102: U901.72 44.12,27.43 43.81,27.13 43.81,26.42 40.49,23.09 33.43,23.09 31.78,21.44 31.78,8.76 33.43,7.11 33.43,4.22 32.13,2.92
LCD-PWM: length 147.5
  TOP w0.102: v1(119.89,56.13) 119.76,56.26 R320.1 R319.1 ; v1(34.54,10.41) 34.54,10.79 33.53,11.81 33.53,21.13 34.75,22.35 41.12,22.35 43.66,24.89 U901.74 46.1,24.89 46.35,25.15 46.35,35.56 47.24,36.45 47.24,52.35 47.98,53.09 49.37,53.09 50.37,54.08 v1(50.37,54.48)
  BOTTOM w0.102: RL48.1 20.83,12.83 21.97,11.68 28.7,11.68 30.48,9.91 34.04,9.91 v1(34.54,10.41) ; v1(50.37,54.48) 50.85,54.97 78.98,54.97 80.35,56.34 82.6,56.34 85.67,59.41 96.64,59.41 97.78,58.27 113.42,58.27 113.64,58.04 117.98,58.04 v1(119.89,56.13)
LCD-RST: length 2.1
  TOP w0.102: RL32.1 120.95,52.16 R342.2 RL55.2
LCD-RST-1: length 11.1
  TOP w0.102: RL32.2 RL44.2 CL19.1 120.95,48.34 122.94,46.35 122.94,45.29 123.16,45.06 J7.24 125.6,45.06 125.84,44.82 v1(125.84,44.78)
  BOTTOM w0.102: v1(125.84,44.78) 125.84,44.81 126.36,45.34 TP65.1
LCD-VSYNC: length 40.6
  TOP w0.102: v1(32.51,6.99) 31.22,8.28 31.22,21.95 32.89,23.62 40.16,23.62 43.23,26.7 43.23,28.32 43.61,28.7 U901.71
  BOTTOM w0.102: 37.21,2.92 35.94,4.19 33.78,4.19 33.4,4.57 33.4,6.1 v1(32.51,6.99)
LED0/CFG-EXT: length 8.8
  TOP w0.102: v1(30.48,68.83) 30.48,68.96 30.9,69.38 RM27.2 30.95,69.4 RM33.2 RM28.2 29.13,69.37 CM15.2 28.19,69.32 28.19,67.55 27.15,66.51 26.76,66.51 26.4,66.16 UM1.32
  BOTTOM w0.102: v1(30.48,68.83) 31.01,69.37 RM26.1
LED1/CFG-LDO0: length 57.7
  TOP w0.254: UM1.33 26,66.42 26.38,66.79 26.99,66.79 27.02,66.83 27.07,66.83 27.66,67.42 27.66,70.97 28.19,71.5 29.38,71.5 CM24.2
  TOP w0.406: CM24.2 v1(30.61,72.09) 30.63,72.07 RM29.1
  BOTTOM w0.254: TP85.1 4.95,53.12 U19.14
  BOTTOM w0.406: RM29.1 30.63,72.07 v1(30.61,72.09) 30.18,72.09 29.46,71.37 21.34,71.37 20.19,70.23 20.19,64.01 20.98,63.22 20.98,60.5 21.01,60.47 21.01,60.12 20.45,59.56 20.45,57.02 14.1,50.67 5.97,50.67 TP85.1
LED2/CFG-LDO1: length 37.4
  TOP w0.254: CM23.2 27.3,71.58 27.3,67.61 26.84,67.15 26.13,67.15 25.6,66.62 UM1.34
  TOP w0.406: RM31.1 28.48,72.07 v1(28.42,72.01) 28.34,72.09 CM23.2
  BOTTOM w0.406: RM31.1 28.48,72.07 v1(28.42,72.01) 17.91,72.01 16.26,70.36 12.45,70.36 11.68,71.12 5.84,71.12 TP86.1 3.54,68.82 U19.11
LED-: length 3.8
  BOTTOM w0.508: J82.19 18.75,7.32 RL49.2
LED-REC: length 57.9
  TOP w0.102: U901.54 44.61,50.29 40.9,46.58 40.9,33 40.52,32.61 31.27,32.61 30.62,31.97 30.62,28.32 20.2,17.9 15.23,17.9 14.73,17.4 14.73,16.51 15.07,16.17 RL12.2 RL14.2 RL13.2
LINEINL: length 6.6
  TOP w0.152: U901.93 63.88,17.78 65.02,16.64 v1(67.95,16.64)
  BOTTOM w0.152: C75.1 68,16.58 v1(67.95,16.64)
LINEINR: length 7
  TOP w0.152: U901.94 65.15,17.78 65.79,17.14 68.96,17.14 v1(69.6,16.51)
  BOTTOM w0.152: v1(69.6,16.51) 69.67,16.58 C384.1
LINEOUTL: length 8.9
  TOP w0.152: U901.91 61.34,13.08 v1(59.82,11.56)
  BOTTOM w0.152: C183.2 v1(59.82,11.56)
LINEOUTR: length 8.7
  TOP w0.152: v1(61.47,11.56) 62.61,12.7 U901.92
  BOTTOM w0.152: C470.1 v1(61.47,11.56)
MBIAS: length 19
  TOP w0.254: v1(43.56,12.19) 44.45,12.19 47.52,15.27 55.02,15.27 57.53,17.78 57.53,18.97
  BOTTOM w0.254: v1(43.56,12.19) 43.43,12.06 R19.2 C49.1
MDC: length 49.2
  TOP w0.102: UM1.13 24,60.71 23.59,60.29 23.59,59.55 v1(23.57,59.54)
  BOTTOM w0.102: v1(23.57,59.54) 24.23,59.54 24.72,60.03 26.7,60.03 26.8,60.13 26.8,61.18 30.36,64.74 37.65,64.74 39.59,66.68 42.26,66.68 43.39,67.82 65.96,67.82 RM8.1
MDI0+: length 11.3
  TOP w0.097: UM1.1 22.23,65.26 22.19,65.22 18.86,65.22 18.37,65.7 14.04,65.7 U19.2
  BOTTOM w0.097: U19.2 13.9,65.65 TP77.1
MDI0-: length 9.4
  TOP w0.097: U19.3 16.49,65.09 16.78,65.38 18.24,65.38 18.73,64.9 22.19,64.9 22.23,64.86 UM1.2
  BOTTOM w0.097: U19.3 18.6,64.34 TP78.1
MDI1+: length 11.4
  TOP w0.097: U19.4 19.63,63.07 20.62,64.06 UM1.4
  BOTTOM w0.097: U19.4 11.71,63.07 TP76.1
MDI1-: length 11.3
  TOP w0.097: UM1.5 20.67,63.66 19.76,62.75 18.46,62.75 17.91,62.2 17.91,60.67 U19.7
  BOTTOM w0.097: U19.7 18.64,59.26 TP75.1
MDI2+: length 11
  TOP w0.097: v1(19.91,62.23) 19.92,62.23 20.95,63.26 22.15,63.26 22.23,63.18 22.54,63.18 UM1.6
  BOTTOM w0.097: TP74.1 16.8,62.11 U19.5 16.49,61.12 16.69,60.92 19.7,60.92 20.04,61.26 20.04,62.1 v1(19.91,62.23)
MDI2-: length 12.6
  TOP w0.097: UM1.7 22.1,62.86 22.02,62.94 21.08,62.94 20.42,62.28 v1(20.42,62.23)
  BOTTOM w0.097: v1(20.42,62.23) 20.36,62.17 20.36,61.13 19.84,60.6 14.03,60.6 U19.6 13.94,60.53 TP73.1
MDI3+: length 12.7
  TOP w0.097: UM1.9 22.23,62.06 22.19,62.02 21.5,62.02 17.53,58.04 14,58.04 U19.8
  BOTTOM w0.097: TP72.1 13.57,58.36 U19.8
MDI3-: length 10.9
  TOP w0.097: U19.9 16.65,56.72 21.63,61.7 22.19,61.7 22.23,61.66 UM1.10
  BOTTOM w0.097: TP71.1 17.3,57.53 U19.9
MDIO: length 43.2
  TOP w0.102: UM1.14 24.4,60.41 v1(24.35,60.36) 24.13,60.14 RM16.1
  BOTTOM w0.102: v1(24.35,60.36) 25.38,60.36 30.16,65.15 37.48,65.15 39.42,67.09 42.09,67.09 43.33,68.33 60.46,68.33 60.67,68.54 RM9.1
MIC1N-MIC: length 6.7
  BOTTOM w0.254: MIC1.2 45.91,5.46 45.09,5.46 44.53,6.01 D10.2 C89.2 44.37,7.15 C88.1 44.32,7.92 C58.1 44.34,8.85 R23.2
MIC1P-MIC: length 5.8
  BOTTOM w0.254: MIC1.1 44.9,4.68 D35.2 C83.1 43.52,7.02 C88.2 43.46,7.93 C52.1 43.44,8.85 R20.2
MICIN1N: length 20.8
  TOP w0.102: v1(44.83,10.29) 44.83,10.67 45.85,11.68 45.85,12.06 48.46,14.68 56.62,14.68 59.54,17.59 59.54,18.87 59.64,18.97 U901.90
  BOTTOM w0.102: v1(44.83,10.29) 44.32,9.78 C58.2
MICIN1P: length 21.2
  TOP w0.102: U901.89 59.23,18.97 59.33,18.87 59.33,17.68 56.54,14.88 48.38,14.88 45.64,12.15 45.64,11.77 44.16,10.29 v1(44.07,10.29)
  BOTTOM w0.102: v1(44.07,10.29) 43.5,9.71 C52.2
MICRO-USB0-DM: length 61.4
  TOP w0.114: U51.6 37.63,46.63 37.83,46.82 38.02,46.82 38.18,46.67 38.18,46.18 37.85,45.85 35.51,45.85 34.54,44.88 34.54,35.18 33.15,33.78 23.49,33.78 22.61,32.89 22.61,22.35 19.56,19.3 11.63,19.3 8.38,16.05 8.38,15.39 8.26,15.27 8.11,15.27 8,15.38 8,15.84 7.89,15.96 D25.1 7.49,15.58 7.38,15.46 5.57,15.46 5.4,15.64 USB1.2
MICRO-USB0-DP: length 61.4
  TOP w0.114: USB1.3 5.4,14.99 5.57,15.16 7.24,15.16 D26.1 7.56,14.97 8.39,14.97 8.68,15.26 8.68,15.92 11.76,19 19.68,19 22.91,22.23 22.91,32.77 23.62,33.48 33.27,33.48 34.85,35.05 34.85,44.75 35.64,45.54 37.97,45.54 38.48,46.05 38.48,46.79 38.15,47.12 U51.7
MIPI-DSI-CKN: length 39
  TOP w0.097: v1(127.13,37.21) 126.87,37.47 124.33,37.47 124.24,37.56 J7.9 123.29,37.56 123.2,37.47 122.88,37.47 121.86,38.49 121.86,40.01 118.34,43.52 112.25,43.52 108.56,47.21 100.22,47.21 96.34,51.09 96.11,51.09 96.02,51.18 96.02,51.47 95.92,51.56 U901.143
MIPI-DSI-CKP: length 40.3
  TOP w0.097: U901.142 95.92,50.29 96.02,50.39 96.02,50.67 96.11,50.77 96.21,50.77 100.09,46.89 108.43,46.89 112.12,43.21 118.21,43.21 121.54,39.88 121.54,38.35 122.74,37.15 123.2,37.15 123.29,37.06 J7.8 124.24,37.06 124.33,37.15 126.69,37.15 126.98,36.86 127.92,36.86 v1(128.27,37.21)
MIPI-DSI-D0N: length 37.6
  TOP w0.097: v1(127.13,33.66) 126.81,33.66 126.09,34.37 124.56,34.37 124.38,34.56 J7.3 123.69,34.48 121.54,34.48 120.87,35.16 120.87,36.28 116.31,40.83 111.13,40.83 107.87,44.09 97.94,44.09 97.31,43.47 96.11,43.47 96.02,43.56 96.02,43.85 95.92,43.94 U901.137
MIPI-DSI-D0P: length 38.7
  TOP w0.097: U901.136 95.92,42.67 96.02,42.77 96.02,43.05 96.11,43.15 97.45,43.15 98.07,43.78 107.73,43.78 111,40.51 116.18,40.51 120.55,36.14 120.55,35.03 121.41,34.16 123.66,34.16 J7.2 125.96,34.06 126.75,33.27 127.76,33.27 v1(128.14,33.66)
MIPI-DSI-D1N: length 37.1
  TOP w0.097: U901.139 95.92,46.48 96.02,46.39 96.02,46.1 96.11,46.01 96.68,46.01 97.57,45.12 108.14,45.12 111.54,41.73 117.07,41.73 121.83,36.97 121.83,36.48 122.34,35.97 123.2,35.97 123.29,36.06 J7.6 124.28,36.06 124.94,35.4 127.09,35.4 v1(127.13,35.43)
MIPI-DSI-D1P: length 38.1
  TOP w0.097: U901.138 95.92,45.21 96.02,45.31 96.02,45.59 96.11,45.69 96.55,45.69 97.43,44.81 108.01,44.81 111.4,41.41 116.94,41.41 121.51,36.84 121.51,36.35 122.21,35.65 123.2,35.65 123.29,35.56 J7.5 124.34,35.56 124.81,35.08 127.79,35.08 v1(128.14,35.43)
MIPI-DSI-D2N: length 36.5
  TOP w0.097: U901.141 95.92,49.02 96.02,48.93 96.02,48.64 96.11,48.55 96.81,48.55 99.19,46.16 108.34,46.16 111.89,42.61 117.76,42.61 120.75,39.62 v1(120.9,39.62) ; v1(122.68,39.09) 122.81,38.97 123.2,38.97 123.29,39.06 J7.12 124.4,39.06 124.59,38.87 126.89,38.87 v1(127,38.99)
  BOTTOM w0.097: v1(122.68,39.09) 122.55,38.97 121.44,38.97 120.9,39.5 v1(120.9,39.62)
MIPI-DSI-D2P: length 37.8
  TOP w0.097: U901.140 95.92,47.75 96.02,47.85 96.02,48.13 96.11,48.23 96.68,48.23 99.06,45.85 108.2,45.85 111.76,42.29 117.63,42.29 120.52,39.4 v1(120.52,39.24) ; v1(122.68,38.52) 122.81,38.65 123.2,38.65 123.29,38.56 J7.11 127.84,38.56 v1(128.27,38.99)
  BOTTOM w0.097: v1(120.52,39.24) 120.55,39.27 120.68,39.27 121.3,38.65 122.55,38.65 v1(122.68,38.52)
MIPI-DSI-D3N: length 38.2
  TOP w0.097: v1(127.13,40.77) 127.13,40.51 126.99,40.37 124.59,40.37 124.4,40.56 J7.15 123.29,40.56 123.2,40.47 122.62,40.47 118.7,44.39 112.65,44.39 108.79,48.25 102.06,48.25 96.68,53.63 96.11,53.63 96.02,53.72 96.02,54.01 95.92,54.1 U901.145
MIPI-DSI-D3P: length 39.1
  TOP w0.097: U901.144 95.92,52.83 96.02,52.93 96.02,53.21 96.11,53.31 96.55,53.31 101.93,47.93 108.66,47.93 112.52,44.07 118.57,44.07 122.49,40.15 123.2,40.15 123.29,40.06 J7.14 127.43,40.06 v1(128.14,40.77)
NALE-EMMC-RST: length 16.3
  TOP w0.102: UM2.12 v1(34.93,15.5) ; U901.77 43.69,21.08 43.05,20.45 v1(43.05,19.43)
  BOTTOM w0.102: v1(34.93,15.5) 37.72,15.5 38.23,16 41.03,16 41.53,15.5 42.17,15.5 42.7,16.03 42.7,19.07 43.05,19.43 v1(43.05,19.43)
NDQ0-EMMC-D7: length 20.6
  TOP w0.102: v1(41.89,16.15) 41.93,16.15 41.95,16.17 42.44,16.17 42.55,16.05 53.14,16.05 54.99,17.91 54.99,18.97 ; UM2.31 v1(39.09,18.7)
  BOTTOM w0.102: v1(41.89,16.15) 41.4,16.64 41.4,18.16 40.87,18.7 v1(39.09,18.7)
NDQ1-EMMC-D2: length 16.1
  TOP w0.102: 52.45,18.97 52.45,17.91 51.1,16.56 42.62,16.56 42.42,16.76 41.02,16.76 v1(40.64,17.14) ; v1(39.12,17.14) 39.07,17.1 UM2.27
  BOTTOM w0.102: v1(40.64,17.14) v1(39.12,17.14)
NDQ2-EMMC-D6: length 16.2
  TOP w0.102: v1(41.91,17.17) 42.39,17.17 42.7,16.87 50.27,16.87 51.18,17.78 U901.83 ; UM2.33 39.06,19.5 v1(39.12,19.56)
  BOTTOM w0.102: v1(41.91,17.17) 41.91,18.16 41.02,19.05 39.62,19.05 v1(39.12,19.56)
NDQ3-EMMC-D1: length 11.7
  TOP w0.102: v1(40.64,17.91) 42.51,17.91 43.15,17.27 47.5,17.27 48.64,18.41 U901.81 ; UM2.29 v1(39.11,17.9)
  BOTTOM w0.102: v1(40.64,17.91) 39.12,17.91 v1(39.11,17.9)
NDQ4-EMMC-D5: length 18.5
  TOP w0.102: 49.91,18.97 49.91,18.16 48.82,17.07 42.88,17.07 42.42,17.53 v1(41.02,17.53) ; v1(34.92,19.56) 34.98,19.5 UM2.2
  BOTTOM w0.102: v1(41.02,17.53) 41.02,18.04 40.72,18.34 37.81,18.34 37.5,18.65 35.83,18.65 v1(34.92,19.56)
NDQ5-EMMC-D0: length 30.4
  TOP w0.102: U901.85 53.72,17.7 52.27,16.26 42.64,16.26 42.37,16.52 41.07,16.52 40.39,15.83 40.39,13.21 39.75,12.57 35.51,12.57 34.09,14 34.09,16.94 35.04,17.9 UM2.6
NDQ6-EMMC-D4: length 15.7
  TOP w0.102: UM2.4 35.02,18.7 v1(34.92,18.8) ; v1(40.64,19.56) 41.66,19.56 43.31,17.91 45.8,17.91 46.1,18.21 U901.79
  BOTTOM w0.102: v1(40.64,19.56) 39.88,19.56 39.48,19.95 36.18,19.95 35.88,20.25 34.86,20.25 34.42,19.81 34.42,19.18 34.8,18.8 v1(34.92,18.8)
NDQ7-EMMC-D3: length 17.4
  TOP w0.102: v1(34.92,16.26) 34.97,16.3 UM2.10 ; v1(42.29,18.41) 43.23,17.48 46.56,17.48 47.37,18.29 U901.80
  BOTTOM w0.102: v1(42.29,18.41) 42.29,16.05 41.99,15.75 41.66,15.75 41.15,16.26 v1(34.92,16.26)
NRB0-EMMC-CMD: length 12.2
  TOP w0.102: UM2.25 39.51,16.3 39.75,16.54 39.75,20.17 43.21,23.62 U901.75
NRE: length 19
  TOP w0.102: UM2.8 34.67,17.1 34.29,16.71 34.29,14.12 35.46,12.95 39.62,12.95 40,13.34 40,19.56 40.47,20.02 RM50.2
NRE-EMMC-CLK: length 3.8
  TOP w0.102: RM50.1 43.52,22.35 U901.76
NWE-EMMC-DS: length 15.4
  TOP w0.102: UM2.15 34.98,14.3 v1(34.92,14.35) ; v1(43.05,18.92) 43.94,19.81 U901.78
  BOTTOM w0.102: v1(43.05,18.92) 43.05,16 42.29,15.24 41.5,15.24 40.94,15.8 38.4,15.8 37.85,15.24 35.81,15.24 v1(34.92,14.35)
OVCUR1#: length 2.7
  TOP w0.102: R237.2 R263.1 37.04,39.5 U32.21
PA-SHDN: length 51.9
  TOP w0.102: v1(54.48,20.83) 53.98,20.32 52.32,20.32 46.99,25.65 v1(46.99,33.02) ; v1(40.39,33.15) 40.64,33.4 40.64,46.74 44.07,50.16 44.07,51.18 44.45,51.56 U901.53
  BOTTOM w0.102: v1(46.99,33.02) 40.51,33.02 v1(40.39,33.15) ; v1(54.48,20.83) 54.48,14.73 54.86,14.35 R182.2
PH4: length 145.8
  TOP w0.102: v1(88.77,73.34) 88.76,73.34 88.41,73.69 88.12,73.69 87.97,73.53 81.61,73.53 81.3,73.84 81.01,73.84 80.7,73.53 v1(80.64,73.53) ; v1(50.67,60.33) 50.67,55.37 50.16,54.86 48.49,54.86 46.33,52.71 46.33,48.13 45.95,47.75 U901.56 42.73,47.75 41.35,46.38 41.35,32.81 40.62,32.08 35.03,32.08 34.59,31.65 34.59,28.35 34.06,27.81 30.69,27.81 24.89,22.01 24.89,21.84 v1(24.91,21.82) ; v1(18.54,31.11) 18.54,31.5 UU3.4 17.99,32.05 RU13.1
  BOTTOM w0.102: v1(80.64,73.53) 80.49,73.69 79.57,73.69 79.1,74.16 79.1,75.39 71.81,82.68 J56.1 ; v1(88.77,73.34) 88.75,73.34 88.65,73.24 88.65,66.22 87.88,65.46 86.03,65.46 81.31,60.73 56.73,60.73 55.66,59.66 52.22,59.66 51.56,60.33 v1(50.67,60.33) ; v1(24.91,21.82) 20.45,26.29 19.56,26.29 18.54,27.3 v1(18.54,31.11)
PH10: length 153.9
  TOP w0.102: v1(88.27,73.33) 88.19,73.33 88.14,73.28 81.36,73.28 v1(81.15,73.48) ; R549.2 9.36,14.01 9.36,15.58 11.88,18.1 20.12,18.1 28.7,26.69 28.7,31.75 29.77,32.82 39.55,32.82 40.44,33.71 40.44,46.82 43.81,50.2 43.81,52.45 44.2,52.83 U901.52 46.17,52.83 48.4,55.07 49.61,55.07 50.42,55.88 50.42,60.07 v1(50.16,60.33)
  BOTTOM w0.102: v1(81.15,73.48) 81.15,73.65 80.77,74.04 79.5,74.04 79.3,74.24 79.3,75.49 70.99,83.79 67.23,83.79 66.12,82.68 J56.2 ; v1(88.27,73.33) 88.44,73.15 88.44,66.3 87.8,65.66 86.11,65.66 85.95,65.66 81.22,60.93 56.64,60.93 55.65,59.94 52.23,59.94 51.49,60.68 50.53,60.68 50.17,60.33 v1(50.16,60.33)
PHYRST: length 11
  TOP w0.102: UM1.12 23.6,60.81 22.73,59.94 22.16,59.94 22.02,59.81 v1(22,59.81) 22,59.79 CM14.1
  BOTTOM w0.102: Q23.3 19.61,54.24 19.61,54.65 19.9,54.94 RM45.2 20.83,56.43 20.83,58.01 20.98,58.17 20.98,58.77 CM14.1 21.54,59.35 v1(22,59.81)
PHYRSTB: length 65.1
  TOP w0.102: U901.16 75.31,68.33 74.8,67.82 v1(72.52,67.82)
  BOTTOM w0.102: v1(72.52,67.82) 72.14,67.82 70.97,66.65 43.66,66.65 42.67,65.66 40.01,65.66 38.05,63.7 30.76,63.7 27.81,60.76 27.81,59.56 26.8,58.55 24.64,58.55 21.72,55.63 20.87,55.63 RM45.1 19.81,54.57 19.81,53.47 20.53,52.75 Q23.2
PS: length 19.1
  TOP w0.305: L12.1 113.2,51.15 U39.6 113.14,53.09 C291.2 110.91,51.97 C294.2
  TOP w0.508: J11.4 38.52,78.23 ; J11.4 36.66,78.23 ; J11.4 37.59,77.3 ; J11.4 37.59,79.16 ; 40.13,77.3 J11.2 ; J11.2 40.13,79.16 ; J11.2 41.06,78.23 ; J11.2 39.2,78.23
  BOTTOM w0.508: 37.59,77.3 J11.4 ; J11.4 38.52,78.23 ; J11.4 37.59,79.16 ; J11.2 40.13,79.16 ; J11.2 40.13,77.3 ; J11.2 39.2,78.23
  vias: v2(94.91,73.01) v2(94.87,72.26) v2(95.63,73.03) v2(95.63,72.26) v2(111,50.8) v2(111.76,50.8) v2(112.52,51.56) v2(112.52,50.8)
PWKEY: length 7
  BOTTOM w0.102: QL13.3 89.45,38.57 CL67.1 DL52.2 92.02,39.24 U27.3
PWR-LED: length 52.3
  TOP w0.102: U901.55 43.69,49.02 41.15,46.48 41.15,32.89 40.59,32.33 33.25,32.33 32.59,31.67 32.59,28.35 32.26,28.02 30.61,28.02 20.24,17.65 19.81,17.65 19.69,17.53 19.69,15.83 RL57.2 RL6.2 RL56.2
PWRON: length 84.4
  TOP w0.102: v1(88.01,31.88) 88.27,32.13 88.27,48.85 84.33,52.79 84.33,56.3 85.47,57.44 85.47,67.56 86.74,68.83 U901.7 ; RP62.2 CK15.1 124.04,27.77 119.63,23.37 114.81,23.37 112.65,25.53 104.14,25.53 v1(103.89,25.78)
  BOTTOM w0.102: v1(103.89,25.78) 103.89,27.56 103.15,28.3 91.41,28.3 88.01,31.7 v1(88.01,31.88)
REGOUT: length 6.7
  TOP w0.203: UM1.30 28.05,65.26 28.19,65.41
  TOP w0.508: 28.19,65.41 29.42,66.63 CM17.2 30.48,66.63 LM1.1 31.12,66.31 31.83,65.59 RM42.2
RF-IN: length 2.1
  TOP w0.381: U8.11 118.69,73.78 RG3.1
RGMII-CLKIN-125M: length 3.5
  TOP w0.102: v1(74.17,70.1) 74.04,69.98 U901.17
  BOTTOM w0.102: R541.1 74.85,70.1 v1(74.17,70.1) R436.1
RGMII-CLKIN-125M#: length 56.2
  TOP w0.102: RM14.2 25.41,68.48 CM13.1 26.85,68.48 v1(26.87,68.45) ; v1(41.02,68.45) v1(41.02,64.39)
  BOTTOM w0.102: v1(26.87,68.45) 26.92,68.4 29.84,68.4 30.05,68.2 31.12,68.2 31.32,68.4 40.97,68.4 v1(41.02,68.45) ; v1(41.02,64.39) 41.15,64.52 42.93,64.52 43.61,65.2 72.23,65.2 R541.2
RGMII-MDC: length 2.8
  TOP w0.102: U901.23 v1(66.42,70.1)
  BOTTOM w0.102: R442.1 v1(66.42,70.1) 65.79,69.47 R546.1
RGMII-MDC#: length 1.2
  BOTTOM w0.102: R546.2 66.64,69.39 RM8.2
RGMII-MDIO: length 1.9
  TOP w0.102: v1(62.61,70.08) U901.26
  BOTTOM w0.102: RM9.2 v1(62.61,70.08)
RGMII-RXCK: length 3.2
  TOP w0.102: v1(77.22,69.98) 77.85,69.34 U901.14
  BOTTOM w0.102: R434.1 77.85,70.61 v1(77.22,69.98) 76.62,69.39 R537.1
RGMII-RXCK#: length 45.3
  TOP w0.102: RM13.2 35.97,59.52 v1(36.4,59.94)
  BOTTOM w0.102: RM13.2 35.97,59.52 v1(36.4,59.94) 37.08,59.94 40.13,62.99 42.16,62.99 43.66,64.49 72.53,64.49 76.57,68.54 R537.2
RGMII-RXCTL: length 3.9
  TOP w0.102: U901.15 v1(76.58,70.1) 76.81,70.33 77.49,70.33 77.5,70.33 v1(77.85,69.98)
  BOTTOM w0.102: R435.1 v1(76.58,70.1) ; R539.1 v1(77.85,69.98)
RGMII-RXCTL#: length 49.1
  BOTTOM w0.102: RM17.2 35.31,61.42 35.31,59.31 35.56,59.05 38.05,59.05 40.26,61.26 41.19,61.26 43.7,63.78 73.09,63.78 R539.2
RGMII-RXD0: length 2.5
  TOP w0.102: U901.13 v1(79.12,70.1)
  BOTTOM w0.102: R433.1 v1(79.12,70.1) R538.1
RGMII-RXD0#: length 43.2
  TOP w0.102: v1(40.13,60.63) 39.31,60.63 RM15.4
  BOTTOM w0.102: v1(40.13,60.63) 40.56,61.06 41.27,61.06 43.76,63.55 74.14,63.55 R538.2
RGMII-RXD1: length 2.5
  TOP w0.102: U901.12 v1(80.39,70.1)
  BOTTOM w0.102: R535.1 v1(80.39,70.1) R432.1
RGMII-RXD1#: length 45.1
  TOP w0.102: v1(40.77,60.58) 40.58,60.58 40.07,60.07 RM15.3
  BOTTOM w0.102: R535.2 80.39,67.82 79.88,67.31 78.28,67.31 74.3,63.32 43.82,63.32 41.08,60.58 v1(40.77,60.58)
RGMII-RXD2: length 2.5
  TOP w0.102: U901.11 v1(81.66,70.1)
  BOTTOM w0.102: R536.1 v1(81.66,70.1) R431.1
RGMII-RXD2#: length 46.4
  TOP w0.102: v1(39.9,59.57) RM15.2
  BOTTOM w0.102: R536.2 81.66,68.2 80.35,66.89 78.15,66.89 74.35,63.09 43.88,63.09 40.73,59.94 40.28,59.94 v1(39.9,59.57)
RGMII-RXD3: length 2.6
  TOP w0.102: v1(83.06,70.1) 82.93,69.98 U901.10
  BOTTOM w0.102: R430.1 v1(83.06,70.1) R534.1
RGMII-RXD3#: length 47.8
  TOP w0.102: RM15.1 39.46,59.16 40,59.16 v1(40.42,59.58)
  BOTTOM w0.102: v1(40.42,59.58) 40.43,59.59 40.66,59.59 43.96,62.89 74.57,62.89 78.23,66.55 80.52,66.55 82.51,68.54 R534.2
RGMII-TXCK: length 2.7
  TOP w0.102: v1(72.9,70.1) 72.77,69.98 U901.18
  BOTTOM w0.102: R441.1 v1(72.9,70.1) 72.9,69.64 R545.1
RGMII-TXCK#: length 0.9
  BOTTOM w0.102: R545.2 RM12.2
RGMII-TXCTL: length 2.6
  TOP w0.102: U901.25 v1(63.88,70.1)
  BOTTOM w0.102: R522.1 v1(63.88,70.1) R547.1
RGMII-TXCTL#: length 1.2
  BOTTOM w0.102: R547.2 64.73,69.39 RM54.2
RGMII-TXD0: length 2.7
  TOP w0.102: U901.22 v1(67.69,70.1)
  BOTTOM w0.102: R440.1 67.31,70.48 v1(67.69,70.1) R544.1
RGMII-TXD0#: length 1.3
  BOTTOM w0.102: R544.2 68.09,68.94 RM5.1
RGMII-TXD1: length 3.3
  TOP w0.102: v1(68.33,70.1) 68.96,69.47 U901.21
  BOTTOM w0.102: v1(68.33,70.1) 68.2,70.23 R439.1 69.05,71.54 R543.1
RGMII-TXD1#: length 1.9
  BOTTOM w0.102: RM5.2 69.47,69.47 69.09,69.85 R543.2
RGMII-TXD2: length 3.1
  TOP w0.102: U901.20 v1(70.23,70.1)
  BOTTOM w0.102: R542.1 70.02,70.7 R438.1 69.98,70.36 v1(70.23,70.1)
RGMII-TXD2#: length 2.1
  BOTTOM w0.102: RM5.3 69.97,69.31 70.87,70.21 R542.2
RGMII-TXD3: length 2.6
  TOP w0.102: v1(71.63,70.1) 71.5,69.98 U901.19
  BOTTOM w0.102: R540.1 v1(71.63,70.1) 71.75,70.23 R437.1
RGMII-TXD3#: length 1.2
  BOTTOM w0.102: RM5.4 71.22,68.94 R540.2
RSET: length 2.4
  TOP w0.102: R50.1 22.9,67.52 23.49,66.93 23.49,66.41 23.6,66.3 UM1.39
RXC/PHYAD1: length 11
  TOP w0.102: RM13.1 34.82,60.37 RM38.1 v1(34.78,61.09) 34.42,61.09 33.27,62.23 29.59,62.23 27.76,64.06 UM1.27
  BOTTOM w0.102: RM38.1 v1(34.78,61.09)
RXCTL/PHYAD2: length 9.9
  TOP w0.102: UM1.26 27.81,63.66 29.44,62.03 32.84,62.03 v1(33.89,60.98) RM40.1
  BOTTOM w0.102: RM17.1 34.63,61.72 v1(33.89,60.98) RM40.1
RXD0/RXDLY: length 16
  TOP w0.102: RM15.5 37.98,60.72 37.31,60.05 37.31,59.41 36.27,58.37 33.83,58.37 33.4,58.8 33.4,60.01 RM24.1 33,61.07 33,61.07 v1(33,61.08) 32.26,61.82 29.24,61.82 27.8,63.26 UM1.25
  BOTTOM w0.102: RM24.1 33,61.07 v1(33,61.08)
RXD1/TXDLY: length 15.9
  TOP w0.102: RM15.6 37.84,60.07 37.52,59.74 37.52,59.23 36.45,58.17 33.02,58.17 32.6,58.59 32.6,59.93 RM22.1 32.11,61.02 v1(32.13,61.04) 32.13,61.29 31.83,61.59 29.08,61.59 27.82,62.86 UM1.24
  BOTTOM w0.102: RM22.1 32.11,61.02 v1(32.13,61.04)
RXD2/PLLOFF: length 15.9
  TOP w0.102: RM15.7 37.87,59.57 37.72,59.41 37.72,59.05 36.58,57.91 32.38,57.91 31.71,58.59 31.71,59.93 RM18.1 31.22,60.7 31.51,60.99 v1(31.51,60.99) 31.18,61.33 28.97,61.33 27.84,62.46 UM1.23
  BOTTOM w0.102: RM18.1 31.22,60.7 31.51,60.99 v1(31.51,60.99)
RXD3/PHYAD0: length 15.3
  TOP w0.102: RM15.8 37.96,58.92 36.7,57.66 31.88,57.66 30.82,58.72 30.82,59.93 RM36.1 30.33,60.7 30.56,60.93 ; UM1.22 27.86,62.06 28.98,60.93 30.56,60.93 ; v1(30.6,60.97) 30.56,60.93
  BOTTOM w0.102: v1(30.6,60.97) 30.33,60.7 RM36.1
S-TWI1-SCK: length 80
  TOP w0.102: v1(89.79,66.17) 90.3,65.66 90.3,58.17 85.98,53.85 85.98,53.21 92.09,47.1 92.09,21.93 92.94,21.08 U901.119 95.91,21.08 96.49,20.5 97.1,20.5 101.13,16.47 U902.12
  BOTTOM w0.102: v1(89.79,66.17) 89.41,66.55 89.41,76.07 88.9,76.58 87.38,76.58 86.74,77.22 86.74,78.11 87,78.36 87,80.18 R77.1 86.49,81.79 J35.3
S-TWI1-SDA: length 81.5
  TOP w0.102: v1(89.28,66.17) 90.09,65.35 90.09,58.25 85.78,53.93 85.78,53.13 91.82,47.08 91.82,21.91 93.29,20.45 94.82,20.45 U901.118 95.99,19.81 96.29,20.12 96.98,20.12 100.15,16.94 100.15,15.42 100.27,15.3 U902.2
  BOTTOM w0.102: J35.4 85.34,82.17 R78.1 84.84,80.18 84.84,79.13 85.25,78.71 85.75,78.71 86.36,78.11 86.36,77.22 87.26,76.31 88.79,76.31 89.14,75.96 89.14,66.31 v1(89.28,66.17)
